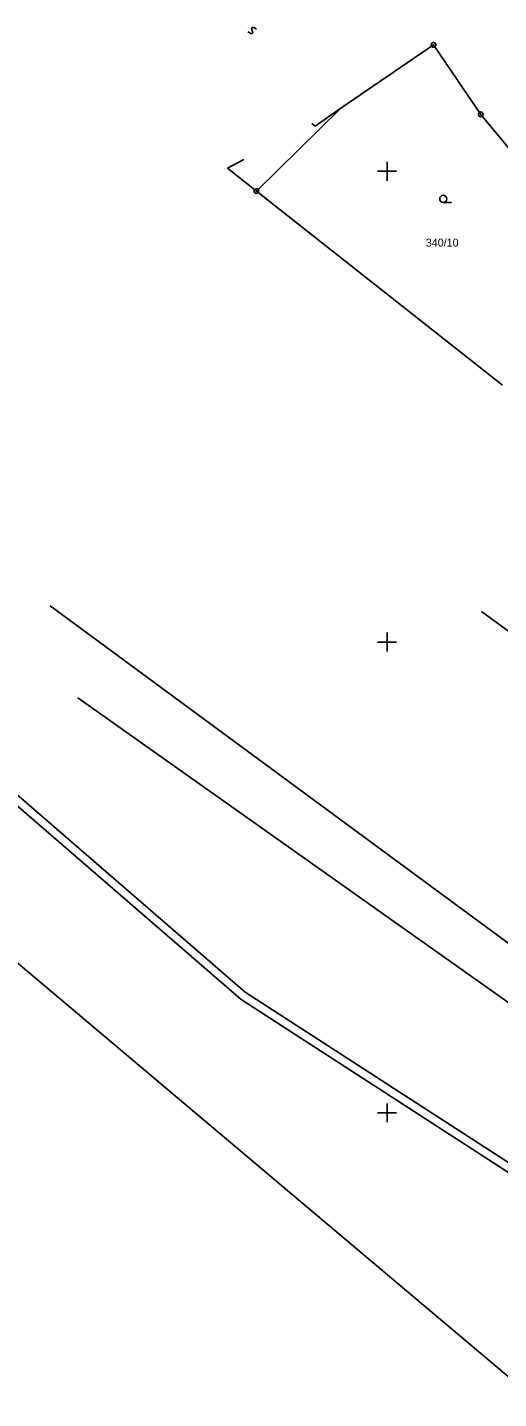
# Model space of a CAD drawing. Extents: x -492379 to -491966, y -1126153 to -1125860.
# Drawn here: x -492322.9 to -492292.9, y -1125948.2 to -1125860.8 of the extents above; entities that cross this region are included whole.
import ezdxf

# ---------------------------------------------------------------- set-up
doc = ezdxf.new("R2010")
doc.units = 0
doc.layers.add('katastrální mapa', color=7, linetype='Continuous')
doc.layers.add('síť', color=7, linetype='Continuous')

msp = doc.modelspace()

# ---------------------------------------------------------------- linework, layer by layer
at = {"layer": 'katastrální mapa'}
for p, q in [((-492308.59, -1125860.83), (-492308.63, -1125860.88)), ((-492308.5, -1125860.83), (-492308.59, -1125860.83)), ((-492308.32, -1125860.94), (-492308.5, -1125860.83)), ((-492308.69, -1125861.22), (-492308.87, -1125861.11)), ((-492308.6, -1125861.22), (-492308.69, -1125861.22)), ((-492308.63, -1125860.88), (-492308.62, -1125860.96)), ((-492308.62, -1125860.96), (-492308.57, -1125861.09)), ((-492308.56, -1125861.17), (-492308.6, -1125861.22)), ((-492308.57, -1125861.09), (-492308.56, -1125861.17)), ((-492297.04, -1125861.94), (-492302.94, -1125865.97)), ((-492297.04, -1125861.94), (-492294.03, -1125866.37)), ((-492308.33, -1125871.26), (-492302.94, -1125865.97)), ((-492304.58, -1125867.12), (-492302.94, -1125865.97)), ((-492304.79, -1125866.95), (-492304.58, -1125867.12)), ((-492294.03, -1125866.37), (-492283.34, -1125879.33)), ((-492310.17, -1125869.81), (-492309.12, -1125869.25)), ((-492310.17, -1125869.81), (-492308.33, -1125871.26)), ((-492308.33, -1125871.26), (-492292.65, -1125883.63)), ((-492296.42, -1125871.98), (-492295.89, -1125871.98)), ((-492307.13, -1125934.3), (-492379.48, -1125873.29)), ((-492344.52, -1125892.34), (-492309.29, -1125922.78)), ((-492337.8, -1125897.44), (-492309.05, -1125922.31)), ((-492321.46, -1125897.7), (-492281.99, -1125926.77)), ((-492293.98, -1125898.06), (-492260.24, -1125922.63)), ((-492319.71, -1125903.55), (-492283.56, -1125929.15)), ((-492309.29, -1125922.78), (-492248.47, -1125962.21)), ((-492309.05, -1125922.31), (-492248.21, -1125961.73)), ((-492225.94, -1126002.74), (-492307.13, -1125934.3))]:
    msp.add_line(p, q, dxfattribs=at)
for centre, radius in [((-492297.04, -1125861.94), 0.15), ((-492297.04, -1125861.94), 0.003), ((-492294.03, -1125866.37), 0.15), ((-492294.03, -1125866.37), 0.003), ((-492308.33, -1125871.26), 0.15), ((-492308.33, -1125871.26), 0.003), ((-492296.42, -1125871.755), 0.225)]:
    msp.add_circle(centre, radius, dxfattribs=at)
at = {"layer": 'síť'}
for p, q in [((-492300, -1125869.4), (-492300, -1125870.6)), ((-492300.6, -1125870), (-492299.4, -1125870)), ((-492300.6, -1125900), (-492299.4, -1125900)), ((-492300, -1125899.4), (-492300, -1125900.6)), ((-492300, -1125929.4), (-492300, -1125930.6)), ((-492300.6, -1125930), (-492299.4, -1125930))]:
    msp.add_line(p, q, dxfattribs=at)

# ---------------------------------------------------------------- texts
at = {"layer": 'katastrální mapa'}
msp.add_text('340/10', height=0.51, dxfattribs=at).set_placement((-492297.53, -1125874.8))

doc.saveas('drawing.dxf')
